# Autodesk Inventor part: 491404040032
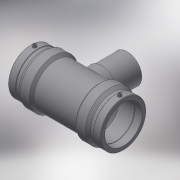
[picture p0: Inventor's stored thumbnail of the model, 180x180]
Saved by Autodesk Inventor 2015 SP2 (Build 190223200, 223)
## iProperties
Created: 2017-06
Part Number: 491404040032
Material: Generic
Description: PLASSON REDUCING TEE 40x32x40
Document SubType Name: Modeling
Designer: KIM
Mass: 153.312 g
Surface Area: 494.901 cm^2
Volume: 153.312 cm^3
Density: 1 g/cm^3
Appearance: Default
Author: KIM
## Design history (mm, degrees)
derived "491404.ipt"
feature "Solid1::491404.ipt"
tag "TaggingFeature1"
body "Solid1"
other parameters: "d2" = 56, "d3" = 43, "d4" = 24, "d5" = 50.4, "d6" = 38, "d8" = 168 deg, "d10" = 17.2, "d11" = 5.73333, "d14" = 17.6296, "d17" = 36, "d19" = 3.52592, "d20" = 168 deg, "d22" = 52.08, "d23" = 56, "d25" = 135 deg, "d26" = 84, "d29" = 47, "d30" = 15, "d31" = 48, "d34" = 5 deg, "d35" = 15, "d39" = 5 deg, "d41" = 4, "d42" = 14, "d43" = 0, "d45" = 4, "d46" = 6, "d47" = 0, "d48" = -75, "d49" = 32, "d51" = 0, "d52" = 25.6, "d54" = 0, "d55" = 50.4, "d56" = 56, "d57" = 42, "d58" = 135 deg, "d59" = 43, "d60" = 43, "d61" = 135 deg, "d62" = 75, "d72" = 54.6, "d73" = 27.3, "d74" = -75, "d75" = 33.6, "d77" = 0, "d78" = 25.6, "d80" = 0, "d81" = 32, "d82" = 47, "d83" = 0, "d84" = 3, "d85" = 0, "d86" = 14.33333, "d87" = 51.0384, "d88" = 5.73333, "d89" = 3, "d90" = 0, "L_1" = 43, "D_" = 56, "A_" = 47, "d_2" = 12, "H_" = 75, "d_1" = 32
